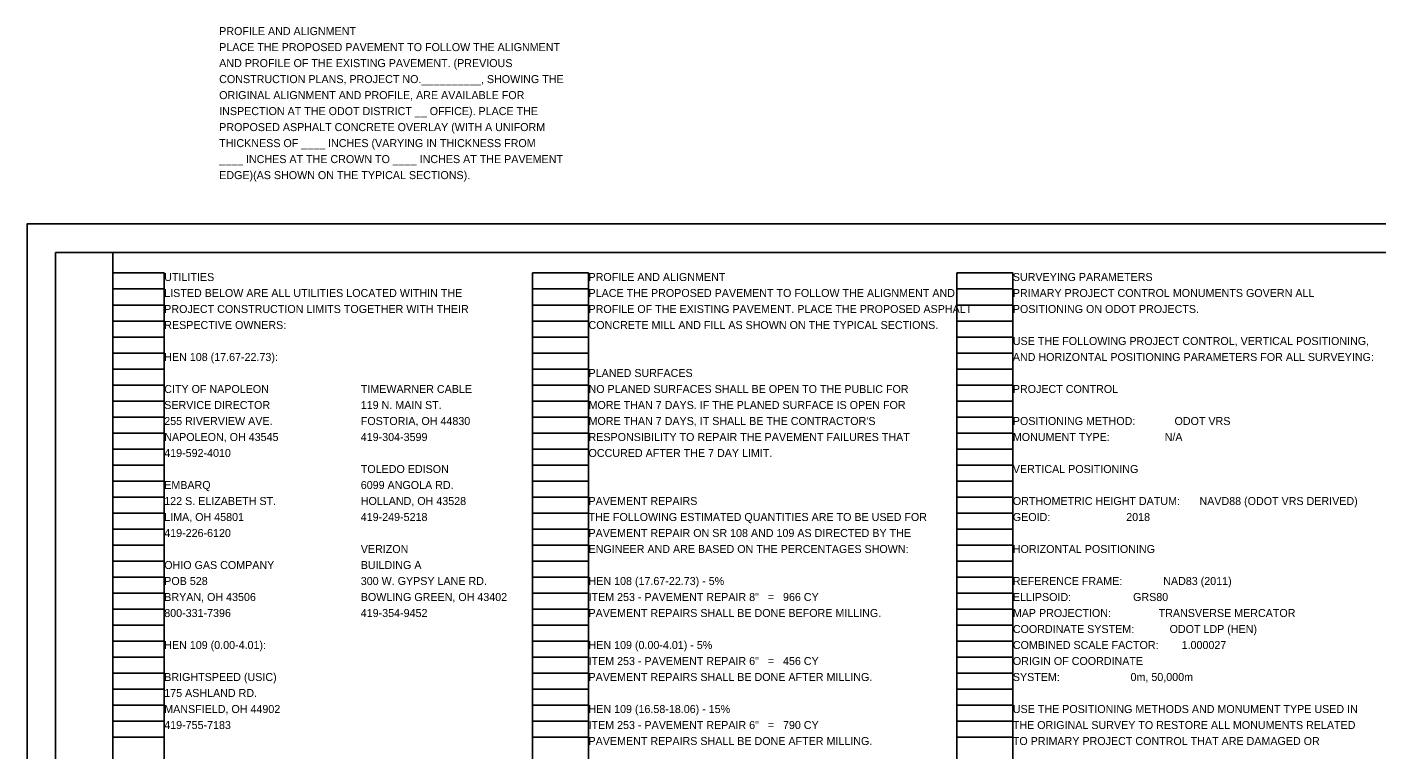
# Model space of a CAD drawing. Extents: x -28.8 to 41.7, y 0 to 25.4.
# Drawn here: x 0 to 23.61, y 12.81 to 25.45 of the extents above; entities that cross this region are included whole.
import ezdxf

# ---------------------------------------------------------------- set-up
doc = ezdxf.new("R2010")
doc.units = 0
for name, color, linetype in [('Default', 7, 'Continuous'), ('SH_Border', 7, 'Continuous'), ('SH_Cut_Line', 7, 'Continuous'), ('SH_Data', 7, 'Continuous'), ('SH_Text', 7, 'Continuous'), ('TX_P_Misc', 7, 'Continuous')]:
    doc.layers.add(name, color=color, linetype=linetype)

msp = doc.modelspace()

# ---------------------------------------------------------------- linework, layer by layer
at = {"layer": 'SH_Border'}
for points in [[(0.5, 21.5), (1.5, 21.5), (1.5, 0.5), (0.5, 0.5)], [(1.5, 21.5), (33.5, 21.5), (33.5, 0.5), (1.5, 0.5)]]:
    msp.add_lwpolyline(points, close=True, dxfattribs=at)
at = {"layer": 'SH_Cut_Line'}
msp.add_lwpolyline([(0, 0), (34, 0), (34, 22), (0, 22)], close=True, dxfattribs=at)
at = {"layer": 'SH_Data'}
for p, q in [((1.5, 0.98), (1.5, 21.14)), ((1.5, 21.14), (2.4, 21.14)), ((2.4, 0.98), (2.4, 21.14)), ((8.84, 0.98), (8.84, 21.14)), ((8.84, 21.14), (9.82, 21.14)), ((9.82, 0.98), (9.82, 21.14)), ((16.26, 0.98), (16.26, 21.14)), ((16.26, 21.14), (17.24, 21.14)), ((17.24, 0.98), (17.24, 21.14)), ((1.5, 20.86), (2.4, 20.86)), ((8.84, 20.86), (9.82, 20.86)), ((16.26, 20.86), (17.24, 20.86)), ((1.5, 20.58), (2.4, 20.58)), ((8.84, 20.58), (9.82, 20.58)), ((16.26, 20.58), (17.24, 20.58)), ((1.5, 20.3), (2.4, 20.3)), ((8.84, 20.3), (9.82, 20.3)), ((16.26, 20.3), (17.24, 20.3)), ((1.5, 20.02), (2.4, 20.02)), ((8.84, 20.02), (9.82, 20.02)), ((16.26, 20.02), (17.24, 20.02)), ((1.5, 19.74), (2.4, 19.74)), ((8.84, 19.74), (9.82, 19.74)), ((16.26, 19.74), (17.24, 19.74)), ((1.5, 19.46), (2.4, 19.46)), ((8.84, 19.46), (9.82, 19.46)), ((16.26, 19.46), (17.24, 19.46)), ((1.5, 19.18), (2.4, 19.18)), ((8.84, 19.18), (9.82, 19.18)), ((16.26, 19.18), (17.24, 19.18)), ((1.5, 18.9), (2.4, 18.9)), ((8.84, 18.9), (9.82, 18.9)), ((16.26, 18.9), (17.24, 18.9)), ((1.5, 18.62), (2.4, 18.62)), ((8.84, 18.62), (9.82, 18.62)), ((16.26, 18.62), (17.24, 18.62)), ((1.5, 18.34), (2.4, 18.34)), ((8.84, 18.34), (9.82, 18.34)), ((16.26, 18.34), (17.24, 18.34)), ((1.5, 18.06), (2.4, 18.06)), ((8.84, 18.06), (9.82, 18.06)), ((16.26, 18.06), (17.24, 18.06)), ((1.5, 17.78), (2.4, 17.78)), ((8.84, 17.78), (9.82, 17.78)), ((16.26, 17.78), (17.24, 17.78)), ((1.5, 17.5), (2.4, 17.5)), ((8.84, 17.5), (9.82, 17.5)), ((16.26, 17.5), (17.24, 17.5)), ((1.5, 17.22), (2.4, 17.22)), ((8.84, 17.22), (9.82, 17.22)), ((16.26, 17.22), (17.24, 17.22)), ((1.5, 16.94), (2.4, 16.94)), ((8.84, 16.94), (9.82, 16.94)), ((16.26, 16.94), (17.24, 16.94)), ((1.5, 16.66), (2.4, 16.66)), ((8.84, 16.66), (9.82, 16.66)), ((16.26, 16.66), (17.24, 16.66)), ((1.5, 16.38), (2.4, 16.38)), ((8.84, 16.38), (9.82, 16.38)), ((16.26, 16.38), (17.24, 16.38)), ((1.5, 16.1), (2.4, 16.1)), ((8.84, 16.1), (9.82, 16.1)), ((16.26, 16.1), (17.24, 16.1)), ((1.5, 15.82), (2.4, 15.82)), ((8.84, 15.82), (9.82, 15.82)), ((16.26, 15.82), (17.24, 15.82)), ((1.5, 15.54), (2.4, 15.54)), ((8.84, 15.54), (9.82, 15.54)), ((16.26, 15.54), (17.24, 15.54)), ((1.5, 15.26), (2.4, 15.26)), ((8.84, 15.26), (9.82, 15.26)), ((16.26, 15.26), (17.24, 15.26)), ((1.5, 14.98), (2.4, 14.98)), ((8.84, 14.98), (9.82, 14.98)), ((16.26, 14.98), (17.24, 14.98)), ((1.5, 14.7), (2.4, 14.7)), ((8.84, 14.7), (9.82, 14.7)), ((16.26, 14.7), (17.24, 14.7)), ((1.5, 14.42), (2.4, 14.42)), ((8.84, 14.42), (9.82, 14.42)), ((16.26, 14.42), (17.24, 14.42)), ((1.5, 14.14), (2.4, 14.14)), ((8.84, 14.14), (9.82, 14.14)), ((16.26, 14.14), (17.24, 14.14)), ((1.5, 13.86), (2.4, 13.86)), ((8.84, 13.86), (9.82, 13.86)), ((16.26, 13.86), (17.24, 13.86)), ((1.5, 13.58), (2.4, 13.58)), ((8.84, 13.58), (9.82, 13.58)), ((16.26, 13.58), (17.24, 13.58)), ((1.5, 13.3), (2.4, 13.3)), ((8.84, 13.3), (9.82, 13.3)), ((16.26, 13.3), (17.24, 13.3)), ((1.5, 13.02), (2.4, 13.02)), ((8.84, 13.02), (9.82, 13.02)), ((16.26, 13.02), (17.24, 13.02))]:
    msp.add_line(p, q, dxfattribs=at)

# ---------------------------------------------------------------- texts
at = {"layer": 'Default'}
for s, p in [('HEN 108 (17.67-22.73) - 5%', (9.82, 15.68)), ('PAVEMENT REPAIRS SHALL BE DONE BEFORE MILLING.', (9.82, 15.12)), ('HEN 109 (0.00-4.01):', (2.4, 14.56)), ('HEN 109 (0.00-4.01) - 5%', (9.82, 14.56)), ('PAVEMENT REPAIRS SHALL BE DONE AFTER MILLING.', (9.82, 14)), ('HEN 109 (16.58-18.06) - 15%', (9.82, 13.44)), ('PAVEMENT REPAIRS SHALL BE DONE AFTER MILLING.', (9.82, 12.88))]:
    msp.add_text(s, height=0.14, dxfattribs=at).set_placement(p)
at = {"layer": 'SH_Text'}
for s, p in [('PROFILE AND ALIGNMENT', (3.361, 25.303)), ('PLACE THE PROPOSED PAVEMENT TO FOLLOW THE ALIGNMENT', (3.361, 25.023)), ('AND PROFILE OF THE EXISTING PAVEMENT. (PREVIOUS', (3.361, 24.743)), ('CONSTRUCTION PLANS, PROJECT NO.__________, SHOWING THE', (3.361, 24.463)), ('ORIGINAL ALIGNMENT AND PROFILE, ARE AVAILABLE FOR', (3.361, 24.183)), ('INSPECTION AT THE ODOT DISTRICT __ OFFICE). PLACE THE', (3.361, 23.903)), ('PROPOSED ASPHALT CONCRETE OVERLAY (WITH A UNIFORM', (3.361, 23.623)), ('THICKNESS OF ____ INCHES (VARYING IN THICKNESS FROM', (3.361, 23.343)), ('____ INCHES AT THE CROWN TO ____ INCHES AT THE PAVEMENT', (3.361, 23.063)), ('EDGE)(AS SHOWN ON THE TYPICAL SECTIONS).', (3.361, 22.783)), ('UTILITIES', (2.4, 21)), ('PROFILE AND ALIGNMENT', (9.82, 21)), ('SURVEYING PARAMETERS', (17.24, 21)), ('LISTED BELOW ARE ALL UTILITIES LOCATED WITHIN THE', (2.4, 20.72)), ('PLACE THE PROPOSED PAVEMENT TO FOLLOW THE ALIGNMENT AND', (9.82, 20.72)), ('PRIMARY PROJECT CONTROL MONUMENTS GOVERN ALL', (17.24, 20.72)), ('PROJECT CONSTRUCTION LIMITS TOGETHER WITH THEIR', (2.4, 20.44)), ('PROFILE OF THE EXISTING PAVEMENT. PLACE THE PROPOSED ASPHALT', (9.82, 20.44)), ('POSITIONING ON ODOT PROJECTS.', (17.24, 20.44)), ('RESPECTIVE OWNERS:', (2.4, 20.16)), ('CONCRETE MILL AND FILL AS SHOWN ON THE TYPICAL SECTIONS.', (9.82, 20.16)), ('USE THE FOLLOWING PROJECT CONTROL, VERTICAL POSITIONING,', (17.24, 19.88)), ('HEN 108 (17.67-22.73):', (2.4, 19.6)), ('AND HORIZONTAL POSITIONING PARAMETERS FOR ALL SURVEYING:', (17.24, 19.6)), ('PLANED SURFACES', (9.82, 19.32)), ('NO PLANED SURFACES SHALL BE OPEN TO THE PUBLIC FOR', (9.82, 19.04)), ('PROJECT CONTROL', (17.24, 19.04)), ('MORE THAN 7 DAYS. IF THE PLANED SURFACE IS OPEN FOR', (9.82, 18.76)), ("MORE THAN 7 DAYS, IT SHALL BE THE CONTRACTOR'S", (9.82, 18.48)), ('POSITIONING METHOD:              ', (17.24, 18.48)), ('ODOT VRS', (20.068, 18.48)), ('RESPONSIBILITY TO REPAIR THE PAVEMENT FAILURES THAT', (9.82, 18.2)), ('MONUMENT TYPE:                   ', (17.24, 18.2)), ('N/A', (19.895, 18.2)), ('OCCURED AFTER THE 7 DAY LIMIT.', (9.82, 17.92)), ('VERTICAL POSITIONING', (17.24, 17.64)), ('PAVEMENT REPAIRS', (9.82, 17.08)), ('ORTHOMETRIC HEIGHT DATUM:        ', (17.24, 17.08)), ('NAVD88 (ODOT VRS DERIVED)', (20.504, 17.08)), ('THE FOLLOWING ESTIMATED QUANTITIES ARE TO BE USED FOR', (9.82, 16.8)), ('GEOID:                           ', (17.24, 16.8)), ('2018', (19.223, 16.8)), ('PAVEMENT REPAIR ON SR 108 AND 109 AS DIRECTED BY THE ', (9.82, 16.52)), ('ENGINEER AND ARE BASED ON THE PERCENTAGES SHOWN:', (9.82, 16.24)), ('HORIZONTAL POSITIONING', (17.24, 16.24)), ('REFERENCE FRAME:                 ', (17.24, 15.68)), ('NAD83 (2011)', (19.87, 15.68)), ('ELLIPSOID:                       ', (17.24, 15.4)), ('GRS80', (19.343, 15.4)), ('MAP PROJECTION:                  ', (17.24, 15.12)), ('TRANSVERSE MERCATOR', (19.79, 15.12)), ('COORDINATE SYSTEM:               ', (17.24, 14.84)), ('ODOT LDP (HEN)', (19.981, 14.84)), ('COMBINED SCALE FACTOR:           ', (17.24, 14.56)), ('1.000027', (20.192, 14.56)), ('ORIGIN OF COORDINATE', (17.24, 14.28)), ('SYSTEM:                          ', (17.24, 14)), ('0m, 50,000m', (19.299, 14)), ('USE THE POSITIONING METHODS AND MONUMENT TYPE USED IN', (17.24, 13.44)), ('THE ORIGINAL SURVEY TO RESTORE ALL MONUMENTS RELATED', (17.24, 13.16)), ('TO PRIMARY PROJECT CONTROL THAT ARE DAMAGED OR', (17.24, 12.88))]:
    msp.add_text(s, height=0.14, dxfattribs=at).set_placement(p)
at = {"layer": 'TX_P_Misc'}
for s, p in [('CITY OF NAPOLEON', (2.4, 19.04)), ('TIMEWARNER CABLE', (5.837, 19.04)), ('SERVICE DIRECTOR', (2.4, 18.76)), ('119 N. MAIN ST.', (5.837, 18.76)), ('255 RIVERVIEW AVE.', (2.4, 18.48)), ('FOSTORIA, OH 44830', (5.837, 18.48)), ('NAPOLEON, OH 43545', (2.4, 18.2)), ('419-304-3599', (5.837, 18.2)), ('419-592-4010', (2.4, 17.92)), ('TOLEDO EDISON', (5.837, 17.64)), ('EMBARQ', (2.4, 17.36)), ('6099 ANGOLA RD.', (5.837, 17.36)), ('122 S. ELIZABETH ST.', (2.4, 17.08)), ('HOLLAND, OH 43528', (5.837, 17.08)), ('LIMA, OH 45801', (2.4, 16.8)), ('419-249-5218', (5.837, 16.8)), ('419-226-6120', (2.4, 16.52)), ('VERIZON', (5.837, 16.24)), ('OHIO GAS COMPANY', (2.4, 15.96)), ('BUILDING A', (5.837, 15.96)), ('POB 528', (2.4, 15.68)), ('300 W. GYPSY LANE RD.', (5.837, 15.68)), ('BRYAN, OH 43506', (2.4, 15.4)), ('BOWLING GREEN, OH 43402', (5.837, 15.4)), ('ITEM 253 - PAVEMENT REPAIR 8"   =   966 CY', (9.82, 15.4)), ('800-331-7396', (2.4, 15.12)), ('419-354-9452', (5.837, 15.12)), ('ITEM 253 - PAVEMENT REPAIR 6"   =   456 CY', (9.82, 14.28)), ('BRIGHTSPEED (USIC)', (2.4, 14)), ('175 ASHLAND RD.', (2.4, 13.72)), ('MANSFIELD, OH 44902', (2.4, 13.44)), ('419-755-7183', (2.4, 13.16)), ('ITEM 253 - PAVEMENT REPAIR 6"   =   790 CY', (9.82, 13.16))]:
    msp.add_text(s, height=0.14, dxfattribs=at).set_placement(p)

doc.saveas('drawing.dxf')
